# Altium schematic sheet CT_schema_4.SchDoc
size 385 x 185 mm
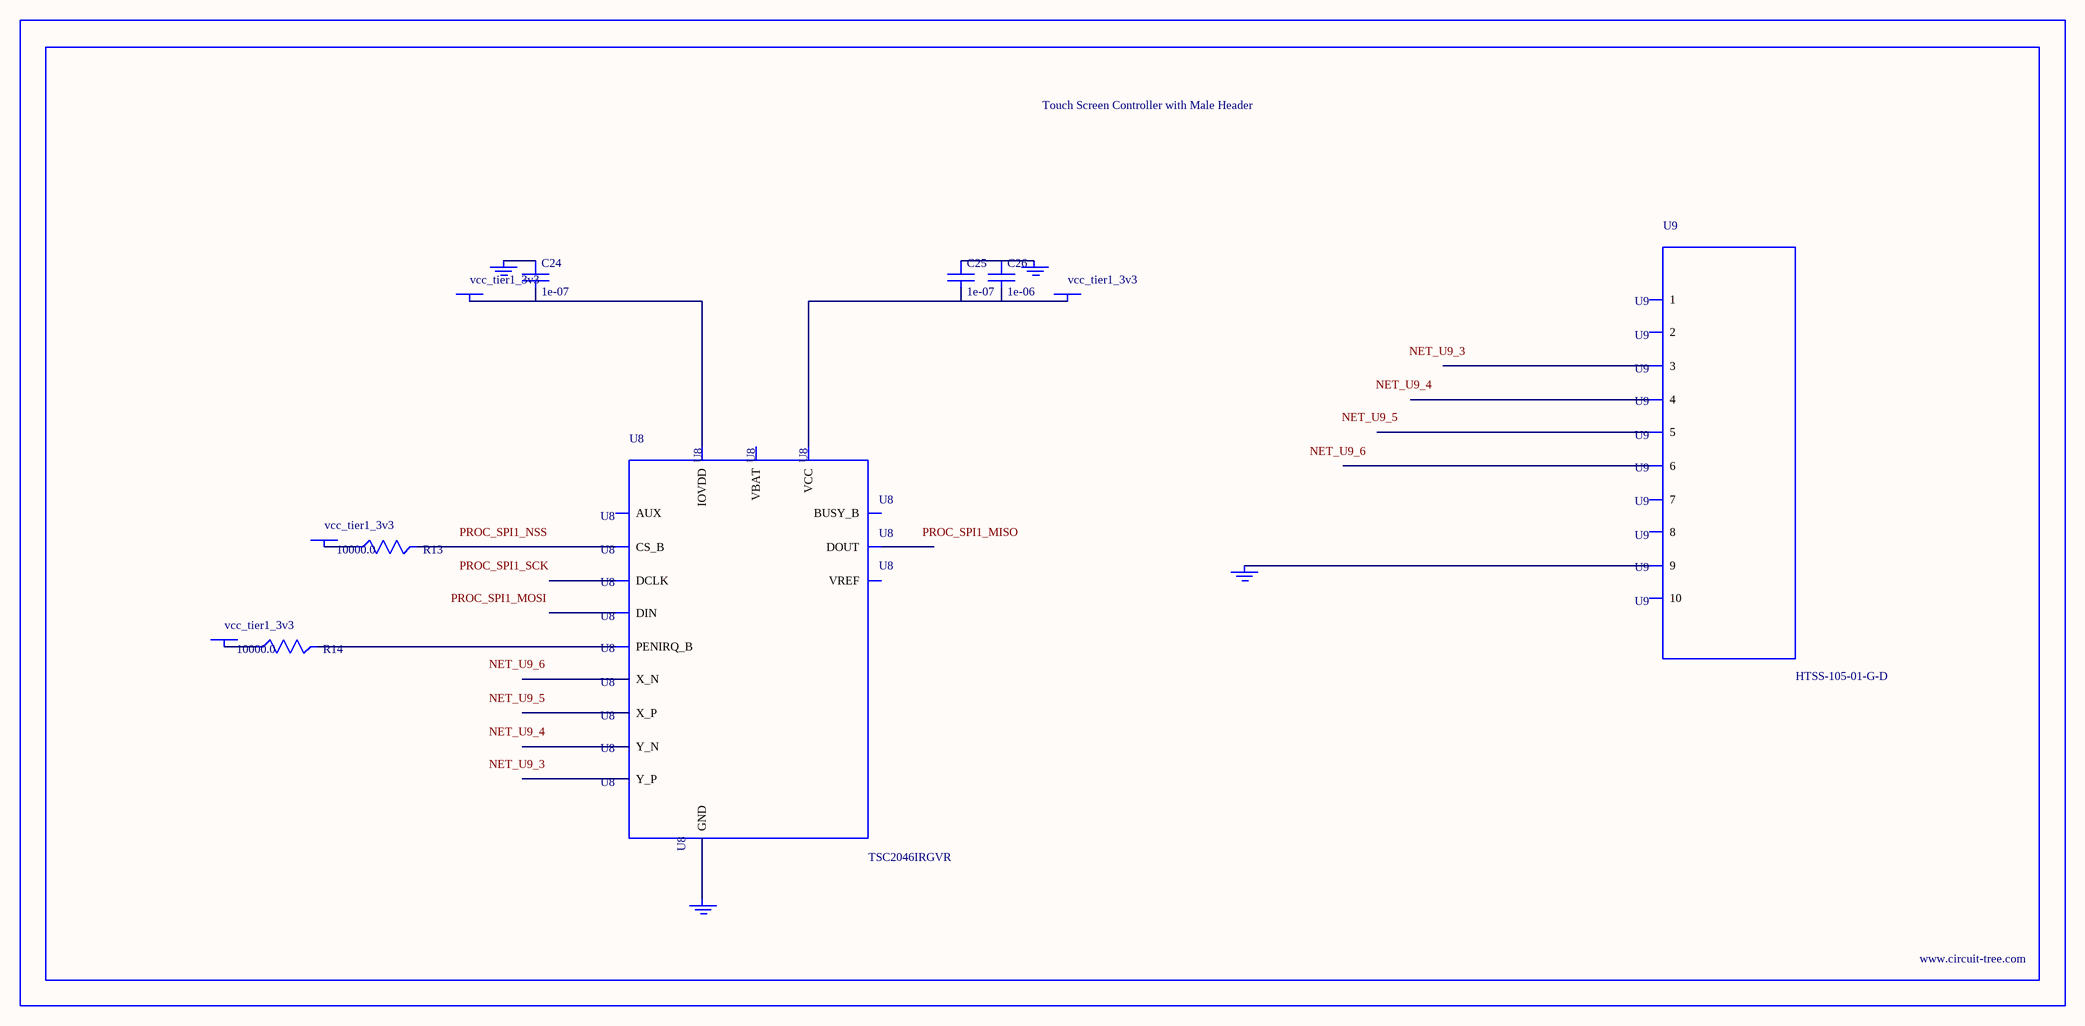
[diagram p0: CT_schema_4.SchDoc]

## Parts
BORDER3  (no value)
C24  1e-07  [C0402]
C25  1e-07  [C0402]
C26  1e-06  [C0603]
GND_INSTANCE_3_0  (no value)
GND_INSTANCE_3_1  (no value)
GND_INSTANCE_3_2  (no value)
GND_INSTANCE_3_3  (no value)
POWER_INSTANCE_3_0  vcc_tier1_3v3
POWER_INSTANCE_3_1  vcc_tier1_3v3
POWER_INSTANCE_3_2  vcc_tier1_3v3
POWER_INSTANCE_3_3  vcc_tier1_3v3
R13  10000.0  [R0603]
R14  10000.0  [R0603]
U8  TSC2046IRGVR  [VQFN-16]
U9  HTSS-105-01-G-D  [HTSS-105-01-G-D]

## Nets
NetC24_1: C24.1 GND_INSTANCE_3_1.0(GND)
NetC24_2: C24.2 POWER_INSTANCE_3_2.0(PWR) U8.14(IOVDD)
NetC25_1: C25.1 C26.1 GND_INSTANCE_3_0.0(GND)
NetC25_2: C25.2 C26.2 POWER_INSTANCE_3_1.0(PWR) U8.5(VCC)
NetGND_INSTANCE_3_2_0: GND_INSTANCE_3_2.0(GND) U8.10(GND)
NetGND_INSTANCE_3_3_0: GND_INSTANCE_3_3.0(GND) U9.9
NetPOWER_INSTANCE_3_0_0: POWER_INSTANCE_3_0.0(PWR) R13.1
NetPOWER_INSTANCE_3_3_0: POWER_INSTANCE_3_3.0(PWR) R14.1
NetR13_2: R13.2 U8.3(CS_B)
NetR14_2: R14.2 U8.15(PENIRQ_B)

Not connected (* = marked no-connect by the designer): U8 1(BUSY_B) 2(DIN) 4(DCLK) 6(X_P) 7(Y_P) 8(X_N) 9(Y_N) 11(VBAT) 12(AUX) 13(VREF) 16(DOUT); U9 1 2 3 4 5 6 7 8 10

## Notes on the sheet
- Labels drawn without touching a wire or pin: NET_U9_3, NET_U9_4, NET_U9_5, NET_U9_6, PROC_SPI1_MISO, PROC_SPI1_MOSI, PROC_SPI1_NSS, PROC_SPI1_SCK

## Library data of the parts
BORDER3 = BORDER_PAGE3
C24 C25 = C0402C104K3RACTU
C26 = C0603C105K3RACTU
GND_INSTANCE_3_0-GND_INSTANCE_3_3 = GND
POWER_INSTANCE_3_0-POWER_INSTANCE_3_3 = PWR
R13 R14 = RC0603JR-0710KL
